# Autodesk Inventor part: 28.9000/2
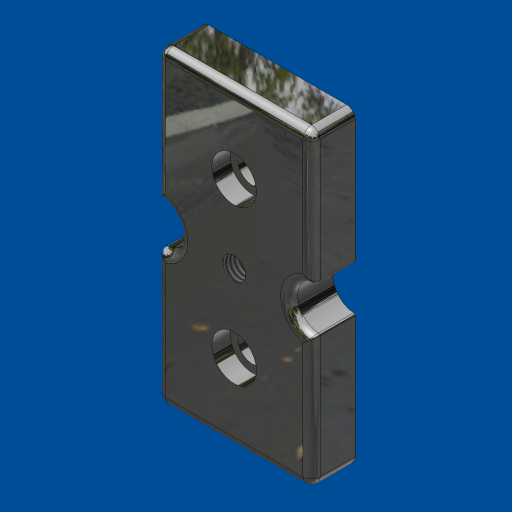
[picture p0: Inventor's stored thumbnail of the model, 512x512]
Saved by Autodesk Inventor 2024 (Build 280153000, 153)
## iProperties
Created: 2022-07
Part Number: 28.9000/2
Material: Aluminum 6061
Document SubType Name: Modeling
Designer: amoles
Density: 2.7 g/cm^3
Appearance: Anodized - Light Gray
Stock Number: 20.9395 AL BSTOCK 3/4" x 2"
Description: ROTATIONAL ELEMENT ROTATING PLATE
Mass: 125.866 g
Surface Area: 118.71 cm^2
Volume: 46.6169 cm^3
FINISH: ETCH & CLEAR ANODIZE
Author: amoles
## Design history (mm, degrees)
sketch "Sketch1"
  geometry: L1 (-22.5, 45)-(22.5, 45); L2 (22.5, 45)-(22.5, -45); L3 (22.5, -45)-(-22.5, -45); L4 (-22.5, -45)-(-22.5, 45); 3 further points
  constraints: 8 end point, 2 midpoint, 2 parallel, 1 horizontal, 1 horizontal alignment, 1 perpendicular, 1 vertical alignment
  dimensions: "d0" = 45 distance of L1.start L1.end; "d1" = 90 distance of L3.end L1.start
extrude "Extrusion1" new body sketch "Sketch1" distance "d2" = 12.7; taper "d3" = 0 deg
sketch "Sketch2"
  geometry: 2 further points
  constraints: 1 coincident
hole "Hole1" sketch "Sketch2" diameter "d4" = 6.647; stored, may be unused: countersink angle "d8" = 82 deg, drill point angle "d10" = 118 deg; dims "d5" = 12.7, "d6" = 13, "d7" = 5.334, "d9" = 25.4
sketch "Sketch3"
  geometry: C1 r 3.323 at (0, 0) reference; 2 further points
  constraints: 2 vertical alignment
  dimensions: "d26" = 22.5 distance of C1.centre point (0, -22.5); "d27" = 22.5 distance of point (0, 22.5) C1.centre
hole "Hole2" sketch "Sketch3" diameter "d13" = 8.5; stored, may be unused: countersink angle "d17" = 82 deg, drill point angle "d19" = 118 deg; dims "d14" = 12.7, "d15" = 13, "d16" = 5.334, "d18" = 25.4
fillet "Fillet1" dims "d31" = 2.4892
sketch "Sketch5"
  geometry: L1 (22.5, 42.511)-(22.5, -42.511) reference; L2 (-22.5, -42.511)-(-22.5, 42.511) reference; C1 r 3.323 at (0, 0) reference; C2 r 6.5 at (-22.5, 0); C3 r 6.5 at (22.5, 0); 4 further points
  constraints: 2 centre point, 2 horizontal alignment
  dimensions: "d33" = 13 diameter of C3; "d34" = 13 diameter of C2; "d35" = 45 distance of C2.centre C3.centre; "d36" = 22.5 distance of C1.centre C2.centre (= 0.5 x d35)
extrude "Extrusion3" cut sketch "Sketch5" distance "d37" = 25.4; taper "d38" = 0 deg
fillet "Fillet3" dims "d39" = 0.5
fillet "Fillet4" dims "d40" = 2.5
body "Solid1"
